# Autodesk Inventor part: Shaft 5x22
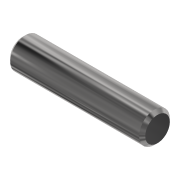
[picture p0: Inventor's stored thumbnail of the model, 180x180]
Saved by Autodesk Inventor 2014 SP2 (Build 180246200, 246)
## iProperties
Created: 2016-02
Part Number: Shaft 5x22
Material: Steel
Document SubType Name: Modeling
Designer: User
Density: 7.85 g/cm^3
Appearance: Steel - Polished
Author: User
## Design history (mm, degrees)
sketch "Sketch1"
  geometry: L1 (-11, 2.5)-(11, 2.5); L2 (11, 2.5)-(11, 0); L3 (11, 0)-(-11, 0); L4 (-11, 0)-(-11, 2.5); 2 further points
  constraints: 8 end point, 2 parallel, 1 coincident, 1 horizontal, 1 midpoint, 1 perpendicular
  dimensions: "d0" = 5 diameter of L1 L3; "d1" = 22 distance of L1.start L1.end
revolve "Revolution1" sketch "Sketch1" stored, may be unused: angle "d2" = 90 deg
chamfer "Chamfer1" distance "d3" = 0.5; stored, may be unused: second distance "d4" = 2, angle "d5" = 45 deg
body "Solid1"
